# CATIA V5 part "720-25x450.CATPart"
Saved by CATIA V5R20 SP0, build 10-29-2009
Part number: 720-25x450
Definition: NONE
Nomenclature: 720-25x450
Source: Unknown
Description: 720-25x450
Bounding box of the stored display mesh (mm): x 0 to 450, y -12.5 to 12.5, z -12.5 to 12.5
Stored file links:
  C:\Users\Utente\Desktop\IO LAVORO\3D X SITO CF\X SITO\720\720-25x450.CATPart
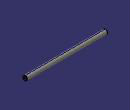
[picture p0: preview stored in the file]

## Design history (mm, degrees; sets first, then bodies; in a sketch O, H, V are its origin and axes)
Body1 "720-25x450" (main body)
  Solid1: solid without history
